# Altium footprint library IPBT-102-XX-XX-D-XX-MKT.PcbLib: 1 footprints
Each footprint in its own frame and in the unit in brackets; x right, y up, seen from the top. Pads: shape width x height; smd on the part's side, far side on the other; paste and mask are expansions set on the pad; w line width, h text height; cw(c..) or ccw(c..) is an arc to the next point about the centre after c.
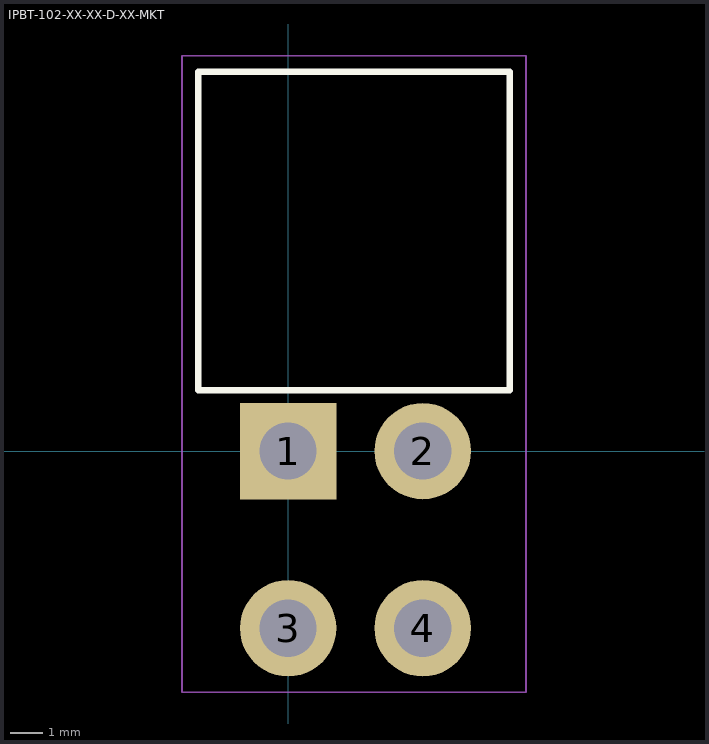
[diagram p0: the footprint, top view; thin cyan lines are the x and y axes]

## IPBT-102-XX-XX-D-XX-MKT [mm] "4.19mm pitch, 4 pin, power header; r/a"
height 10.77
pads (4):
  rect 3x3 / inner round 3 / far side rect 3x3 hole 1.78 mask+0: 1(0,0)
  round 3 hole 1.78 mask+0: 2(4.19,0) 3(0,-5.51) 4(4.19,-5.51)
Top Overlay:
  lines w0.2: -2.8,1.9 6.9,1.9 6.9,11.8 -2.8,11.8 -2.8,1.9
Mechanical 12:
  lines w0.001: -2.8,1.9 6.9,1.9 6.9,11.8 -2.8,11.8 -2.8,1.9
Mechanical 13:
  lines w0.1: -2.8,1.9 6.9,1.9 6.9,11.8 -2.8,11.8 -2.8,1.9
  text ".Designator" at 0.254,0.254 h1.52
Mechanical 15:
  lines w0.05: -3.3,-7.5 7.4,-7.5 7.4,12.3 -3.3,12.3 -3.3,-7.5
